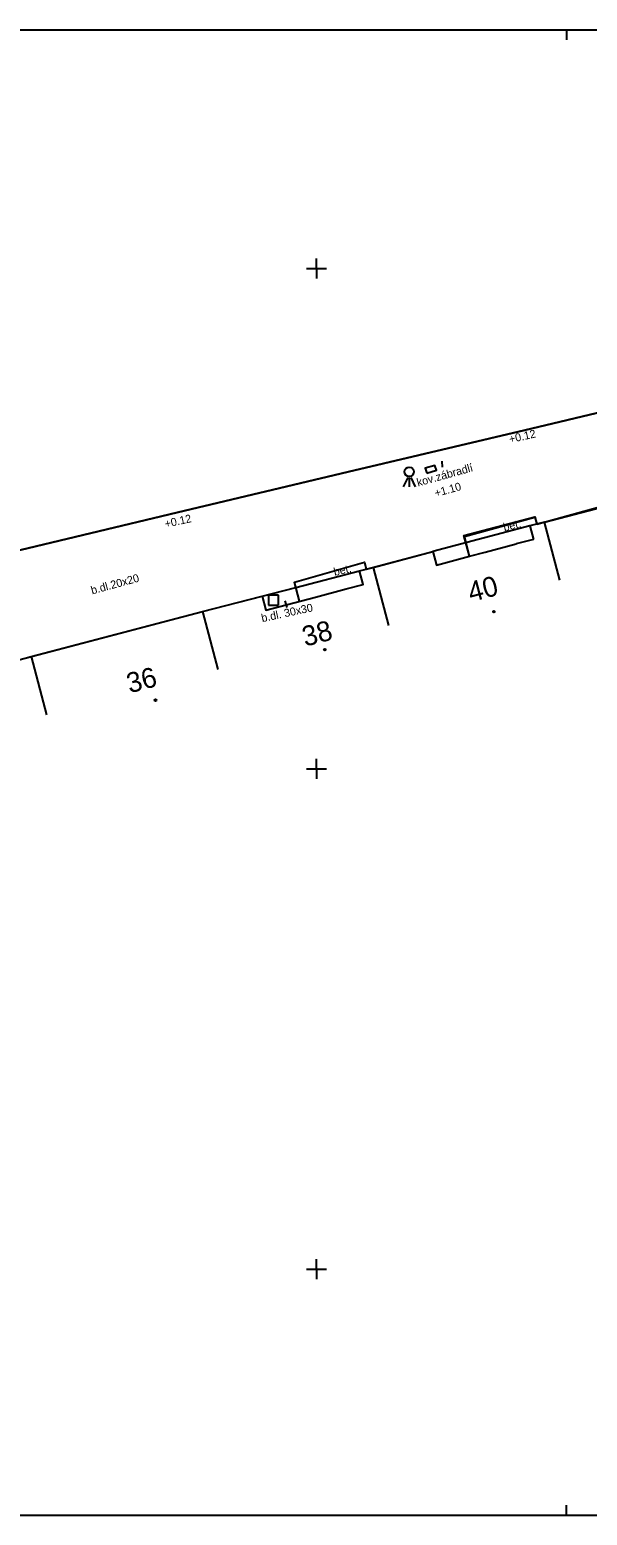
# Model space of a CAD drawing. Extents: x -598468 to -598310, y -1159412 to -1159338.
# Drawn here: x -598389.3 to -598361.5, y -1159412.3 to -1159338.1 of the extents above; entities that cross this region are included whole.
import ezdxf

# ---------------------------------------------------------------- set-up
doc = ezdxf.new("R2010")
doc.units = 0
for name, color, linetype in [('Vrstva 1', 7, 'Continuous'), ('Vrstva 15', 7, 'Continuous'), ('Vrstva 22', 7, 'Continuous'), ('Vrstva 23', 7, 'Continuous'), ('Vrstva 34', 7, 'Continuous'), ('Vrstva 4', 7, 'Continuous'), ('Vrstva 43', 7, 'Continuous'), ('Vrstva 44', 7, 'Continuous'), ('Vrstva 49', 7, 'Continuous'), ('Vrstva 5', 7, 'Continuous'), ('Vrstva 50', 7, 'Continuous'), ('Vrstva 62', 7, 'Continuous'), ('Vrstva 63', 7, 'Continuous'), ('Vrstva 7', 7, 'Continuous')]:
    doc.layers.add(name, color=color, linetype=linetype)

msp = doc.modelspace()

# ---------------------------------------------------------------- linework, layer by layer
at = {"layer": 'Vrstva 1'}
for p, q in [((-598415.033, -1159338.058), (-598362.533, -1159338.058)), ((-598362.533, -1159338.058), (-598362.533, -1159338.558)), ((-598362.533, -1159338.058), (-598310.033, -1159338.058)), ((-598362.533, -1159412.308), (-598362.533, -1159411.808)), ((-598415.033, -1159412.308), (-598362.533, -1159412.308)), ((-598362.533, -1159412.308), (-598310.033, -1159412.308))]:
    msp.add_line(p, q, dxfattribs=at)
at = {"layer": 'Vrstva 15'}
for centre in [(-598366.1519, -1159367.1429), (-598374.5899, -1159369.0459), (-598383.0449, -1159371.5659)]:
    msp.add_circle(centre, 0.0438, dxfattribs=at)
at = {"layer": 'Vrstva 22'}
msp.add_lwpolyline([(-598368.713, -1159359.916), (-598368.731, -1159359.618)], dxfattribs=at)
at = {"layer": 'Vrstva 23'}
for p, q in [((-598376.898, -1159366.325), (-598377.398, -1159366.325)), ((-598377.398, -1159366.325), (-598377.398, -1159366.825)), ((-598377.398, -1159366.825), (-598376.898, -1159366.825)), ((-598376.898, -1159366.825), (-598376.898, -1159366.325))]:
    msp.add_line(p, q, dxfattribs=at)
at = {"layer": 'Vrstva 34'}
msp.add_lwpolyline([(-598369.501, -1159360.217), (-598369.023, -1159360.071), (-598369.097, -1159359.831), (-598369.575, -1159359.977)], close=True, dxfattribs=at)
at = {"layer": 'Vrstva 4'}
for p, q in [((-598367.627, -1159363.391), (-598364.104, -1159362.426)), ((-598364.35, -1159362.862), (-598369.196, -1159364.144)), ((-598363.626, -1159362.671), (-598364.35, -1159362.862)), ((-598364.35, -1159362.862), (-598364.173, -1159363.531)), ((-598364.173, -1159363.531), (-598365.043, -1159363.761))]:
    msp.add_line(p, q, dxfattribs=at)
for points in [[(-598364.104, -1159362.426), (-598364.012, -1159362.773)], [(-598362.859, -1159365.571), (-598363.626, -1159362.671), (-598360.699, -1159361.901), (-598360.522, -1159362.575), (-598357.992, -1159361.909)], [(-598367.366, -1159364.376), (-598367.627, -1159363.391)], [(-598375.862, -1159366.626), (-598376.109, -1159365.671), (-598372.618, -1159364.666), (-598372.525, -1159365.023)], [(-598372.864, -1159365.111), (-598372.181, -1159364.934), (-598369.196, -1159364.144)], [(-598369.196, -1159364.144), (-598369.019, -1159364.813), (-598367.366, -1159364.376)], [(-598367.366, -1159364.376), (-598366.589, -1159364.17)], [(-598377.716, -1159366.368), (-598376.041, -1159365.934), (-598372.864, -1159365.111)], [(-598373.518, -1159366.006), (-598372.685, -1159365.786), (-598372.864, -1159365.111)], [(-598372.181, -1159364.934), (-598371.414, -1159367.834)], [(-598380.703, -1159367.142), (-598377.716, -1159366.368)], [(-598377.716, -1159366.368), (-598377.531, -1159367.068), (-598375.064, -1159366.415)], [(-598389.249, -1159369.392), (-598380.703, -1159367.142), (-598379.939, -1159370.043)], [(-598397.049, -1159374.546), (-598397.782, -1159371.758), (-598397.812, -1159371.645), (-598394.798, -1159370.852), (-598389.553, -1159369.472), (-598389.249, -1159369.392), (-598388.486, -1159372.293)]]:
    msp.add_lwpolyline(points, dxfattribs=at)
at = {"layer": 'Vrstva 44'}
for p, q in [((-598370.449, -1159360.445), (-598370.675, -1159360.897)), ((-598370.375, -1159360.447), (-598370.375, -1159360.897)), ((-598370.3, -1159360.445), (-598370.075, -1159360.897))]:
    msp.add_line(p, q, dxfattribs=at)
msp.add_circle((-598370.375, -1159360.152), 0.234, dxfattribs=at)
at = {"layer": 'Vrstva 49'}
msp.add_lwpolyline([(-598376.476, -1159366.944), (-598376.567, -1159366.595)], dxfattribs=at)
at = {"layer": 'Vrstva 5'}
msp.add_line((-598366.589, -1159364.17), (-598365.043, -1159363.761), dxfattribs=at)
msp.add_lwpolyline([(-598375.064, -1159366.415), (-598373.518, -1159366.006)], dxfattribs=at)
at = {"layer": 'Vrstva 62'}
for p, q in [((-598375, -1159350), (-598375, -1159349.5)), ((-598375.5, -1159350), (-598375, -1159350)), ((-598375, -1159350), (-598374.5, -1159350)), ((-598375, -1159350), (-598375, -1159350.5)), ((-598375.5, -1159375), (-598375, -1159375)), ((-598375, -1159375), (-598375, -1159374.5)), ((-598375, -1159375), (-598374.5, -1159375)), ((-598375, -1159375), (-598375, -1159375.5)), ((-598375, -1159400), (-598375, -1159399.5)), ((-598375.5, -1159400), (-598375, -1159400)), ((-598375, -1159400), (-598374.5, -1159400)), ((-598375, -1159400), (-598375, -1159400.5))]:
    msp.add_line(p, q, dxfattribs=at)
at = {"layer": 'Vrstva 63'}
for points in [[(-598356.442, -1159356.127), (-598364.611, -1159358.068), (-598373.433, -1159360.163), (-598381.966, -1159362.196), (-598399.215, -1159366.328)], [(-598389.553, -1159369.472), (-598380.703, -1159367.142), (-598376.041, -1159365.934), (-598376.109, -1159365.671), (-598372.618, -1159364.666), (-598372.525, -1159365.023), (-598369.196, -1159364.144), (-598369.019, -1159364.813), (-598367.366, -1159364.376), (-598367.649, -1159363.339), (-598364.108, -1159362.404), (-598364.012, -1159362.773), (-598360.694, -1159361.854)]]:
    msp.add_lwpolyline(points, dxfattribs=at)
at = {"layer": 'Vrstva 7'}
for points in [[(-598460.606, -1159380.951), (-598440.32, -1159376.125), (-598425.303, -1159372.541), (-598424.365, -1159372.319), (-598420.776, -1159371.464), (-598419.837, -1159371.24), (-598416.865, -1159370.534), (-598415.902, -1159370.301), (-598412.459, -1159369.48), (-598411.487, -1159369.252), (-598399.215, -1159366.328), (-598381.966, -1159362.196), (-598373.433, -1159360.163), (-598364.611, -1159358.068), (-598356.442, -1159356.127), (-598347.429, -1159354.018), (-598330.181, -1159349.984), (-598327.958, -1159349.509), (-598322.621, -1159348.841), (-598316.937, -1159348.463)], [(-598377.716, -1159366.368), (-598376.041, -1159365.934)]]:
    msp.add_lwpolyline(points, dxfattribs=at)

# ---------------------------------------------------------------- texts
at = {"layer": 'Vrstva 43'}
for s, height, rotation, p in [('40', 1, 14.823842, (-598367.298, -1159366.674)), ('38', 1, 14.825842, (-598375.572, -1159368.9)), ('36', 0.99999, 14.750164, (-598384.335, -1159371.23))]:
    msp.add_text(s, height=height, rotation=rotation, dxfattribs=at).set_placement(p)
at = {"layer": 'Vrstva 49'}
for s, height, rotation, p in [('kov.zábradlí', 0.399996, 15.559881, (-598369.939, -1159360.891)), ('+1.10', 0.4, 15.559881, (-598369.052, -1159361.42)), ('bet.', 0.4, 13.350819, (-598365.63, -1159363.125)), ('b.dl.20x20', 0.39995, 15.260628, (-598386.205, -1159366.282)), ('bet.', 0.4, 13.350819, (-598374.099, -1159365.362)), ('b.dl. 30x30', 0.399942, 12.116097, (-598377.716, -1159367.668))]:
    msp.add_text(s, height=height, rotation=rotation, dxfattribs=at).set_placement(p)
at = {"layer": 'Vrstva 50'}
for p in [(-598365.349, -1159358.724), (-598382.538, -1159362.959)]:
    msp.add_text('+0.12', height=0.4, rotation=12.614311, dxfattribs=at).set_placement(p)

doc.saveas('drawing.dxf')
